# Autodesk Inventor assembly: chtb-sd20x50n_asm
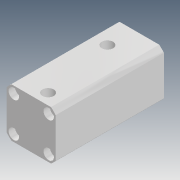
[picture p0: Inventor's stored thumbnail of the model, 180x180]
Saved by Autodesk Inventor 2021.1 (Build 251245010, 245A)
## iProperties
Company: Microsoft
Created: 2018-04
Part Number: chtb-sd20x50n_asm
Description: STEP AP214
Document SubType Name: Assembly
Designer: user
Title: chtb-sd20x50n_asm.STEP
Author: Windows
Revision Number: ÈÎºÎ
Sending System: SolidWorks 2015
Preprocessor: SwSTEP 2.0
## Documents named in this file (4)
- D:\Vault_2016\Projekty\Clamptek\Hydraulic\CHTB\CHTB-20\Inventor\CHTB-SD20x50N\chtb-sd20x50n_asm.iam
- D:\Vault_2016\Projekty\Clamptek\Hydraulic\CHTB\CHTB-20\Inventor\CHTB-SD20x50N\CHTB-SD20X50NBT.ipt
- D:\Vault_2016\Projekty\Clamptek\Hydraulic\CHTB\CHTB-20\Inventor\CHTB-SD20x50N\CHTB-SD20X50NHSG.ipt
- D:\Vault_2016\Projekty\Clamptek\Hydraulic\CHTB\CHTB-20\Inventor\CHTB-SD20x50N\QG.ipt
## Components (3 placed, 3 different names)
1. CHTB-SD20X50NBT_1
2. CHTB-SD20X50NHSG_2
3. QG_3
